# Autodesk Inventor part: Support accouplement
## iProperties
Shininess: 64.0
Length Units: 11269
Angle Units: 11279
Time Units: 11290
Mass Units: 11283
Length Display Precision: 3
Angle Display Precision: 2
Compacted: True
Part Number: Support accouplement
Document SubType Name: Sheet Metal
Created: 2003-05
Material: Par défaut
Designer: Philippe
Density: 0.0
Volumn: 0.0
Area: 0.0
PropertySet Name: Model Information
Control State: 0
Master: False
Checked Out: False
Author: Philippe
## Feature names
1. Plaque1
2. Plaque2
3. Pli1
4. Plaque3
5. Pli2
6. Ouverture1
